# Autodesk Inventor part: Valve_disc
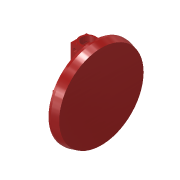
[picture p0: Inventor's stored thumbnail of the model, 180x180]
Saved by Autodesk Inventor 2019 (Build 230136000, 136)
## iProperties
Created: 2019-09
Part Number: Valve_disc
Material: Steel, Alloy
Document SubType Name: Modeling
Designer: Admin
Density: 7.73 g/cm^3
Appearance: Semi-Polished
Author: Admin
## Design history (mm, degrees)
sketch "Sketch1"
  geometry: L1 (123.5, 3.8)-(0, 3.8); L2 (0, 3.8)-(0, 28.8); L3 (0, 28.8)-(118.5, 28.8); L4 (123.5, 10.3)-(123.5, 3.8); L5 (261.841, 0)-(-137.497, 0) reference; L6 (0, -110.595)-(0, 144.471) reference; L7 (269.015, 10.3)-(-178.546, 10.3); L8 (118.5, -59.582)-(118.5, 151.645); L9 (123.5, 10.3)-(118.5, 28.8); 1 further point
  constraints: 18 end point, 4 horizontal, 3 vertical, 2 parallel, 2 point on line, 1 perpendicular
  dimensions: "d0" = 123.5 distance between parallel lines of L2 L4; "d1" = 25 distance between parallel lines of L3 L1; "d2" = 3.8 distance between parallel lines of L5 L1; "d3" = 6.5 distance between parallel lines of L1 L7; "d4" = 5 distance between parallel lines of L4 L8; "d5" = 123.5 distance between parallel lines of L6 L4
revolve "Revolution1" sketch "Sketch1" stored, may be unused: angle "d6" = 90 deg
sketch "Sketch2"
  geometry: L1 (90, 3.8)-(-90, 3.8); L2 (-90, 3.8)-(-90, -32.7); L3 (-90, -32.7)-(90, -32.7); L4 (90, -32.7)-(90, 3.8); L5 (-123.5, 3.8)-(123.5, 3.8) reference; L6 (0, 116.452)-(0, -142.118); 1 further point
  constraints: 10 end point, 2 parallel, 1 horizontal, 1 perpendicular, 1 vertical, 1 other
  dimensions: "d7" = 180 distance of L3.end L2.end; "d8" = 36.5 distance of L2.end L1.end; "d9" = 0 distance between parallel lines of L5 L1
extrude "Extrusion1" join sketch "Sketch2" stored distance "d10" = 44; taper "d11" = 0 deg
sketch "Sketch3"
  geometry: L1 (-123.5, 3.8)-(123.5, 3.8) reference; L2 (0, 131.392)-(0, -179.658) reference; L3 (18.296, -10.2)-(-16.23, -10.2); L4 (22.5, -10.2)-(22.5, 3.8); L5 (-22.5, -10.2)-(-22.5, 3.8); L6 (22.5, 3.8)-(-22.5, 3.8); A1 r 22.5 centre (0, -10.2) between (-22.5, -10.2) and (22.5, -10.2); 1 further point
  constraints: 10 end point, 4 point on line, 2 horizontal, 2 perpendicular, 2 point on circle, 2 vertical, 1 centre point, 1 tangent
  dimensions: "d12" = 14 distance between parallel lines of L1 L3; "d13" = 45 diameter of A1; "d14" = 45 distance between parallel lines of L5 L4
extrude "Extrusion2" join sketch "Sketch3" stored distance "d15" = 232; taper "d16" = 0 deg
sketch "Sketch4"
  geometry: L1 (-0.75, -62.976)-(-0.75, 21.958); L2 (0, -10.2)-(-12.705, -10.2); C1 r 17.45 at (-0.75, -10.2); A1 r 22.5 centre (0, -10.2) between (-22.5, -10.2) and (22.5, -10.2) reference; 1 further point
  constraints: 4 end point, 2 point on line, 1 centre point, 1 horizontal, 1 vertical
  dimensions: "d17" = 0.75 distance from line of L2.start L1; "d18" = 34.9 diameter of C1
extrude "Extrusion3" cut sketch "Sketch4" stored distance "d19" = 272.3625; taper "d20" = 0 deg
workaxis "Work Axis1"
chamfer "Chamfer1" distance "d22" = 15; stored, may be unused: second distance "d23" = 2, angle "d24" = 45 deg
chamfer "Chamfer2" distance "d25" = 15; stored, may be unused: second distance "d26" = 2, angle "d27" = 45 deg
feature "Move Body2"
workplane "Work Plane1"
sketch "Sketch6"
  geometry: L1 (78.605, 98)-(-94.326, 98); L2 (0.75, 116)-(-21.75, 116) reference; L3 (14.75, 122.994)-(14.75, -122.994) reference; L4 (81.335, 76)-(-111.126, 76); L5 (-12.15, 131.038)-(-12.15, -44.547); C1 r 5 at (-12.15, 98); C2 r 5 at (-12.15, 76); 1 further point
  constraints: 6 end point, 4 point on line, 2 centre point, 2 horizontal, 1 vertical
  dimensions: "d38" = 18 distance between parallel lines of L1 L2; "d39" = 22 distance between parallel lines of L4 L1; "d40" = 26.9 distance between parallel lines of L3 L5; "d41" = 10 diameter of C1; "d42" = 10 diameter of C2
sketch "Sketch7"
  geometry: L1 (0, -45)-(-25, -45); L2 (-25, -45)-(-25, 0); L3 (-25, 0)-(0, 0); L4 (0, 0)-(0, -45); A1 r 22.5 centre (0, -22.5) between (-22.5, -22.5) and (0, -45) reference; A2 r 22.5 centre (0, -22.5) between (0, 0) and (0, -45); 1 further point
  constraints: 8 end point, 2 parallel, 2 point on circle, 1 centre point, 1 horizontal, 1 perpendicular, 1 tangent
  dimensions: "d45" = 25 distance of L2.end L3.end
extrude "Extrusion6" join sketch "Sketch7" stored distance "d46" = 45; taper "d47" = 0 deg
extrude "Extrusion7" cut sketch "Sketch6" stored distance "d48" = 76.75; taper "d49" = 0 deg
workaxis "Work Axis2"
workaxis "Work Axis3"
feature "Move Body4"
feature "Move Body5"
feature "Move Body3"
body "Solid1"
other parameters: "d28" = 90 deg, "d30" = 0, "d31" = 0, "d32" = -27.5, "d50" = -90 deg, "d51" = 90 deg
